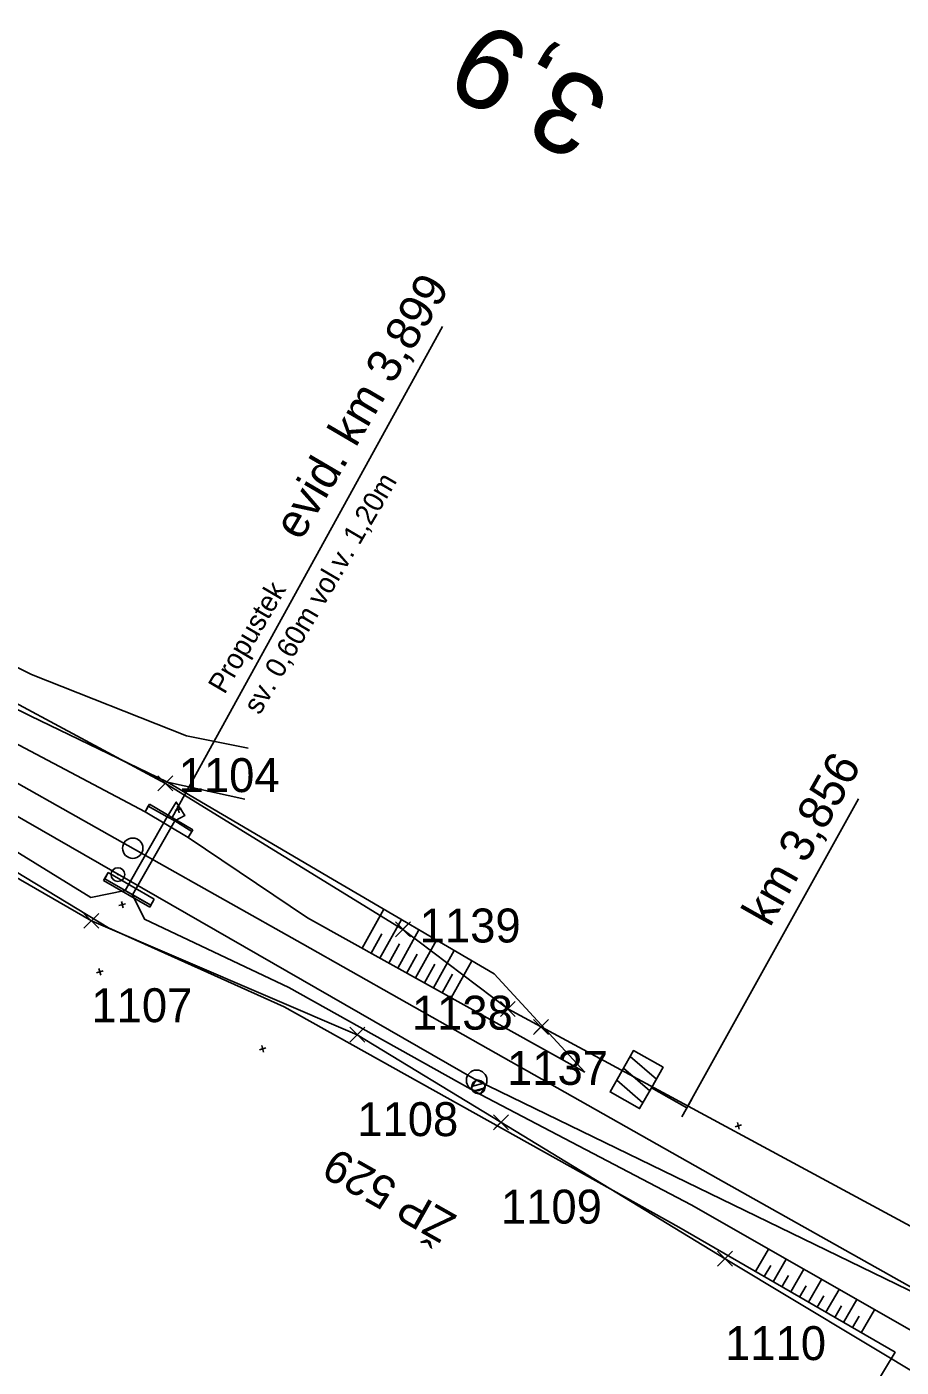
# Model space of a CAD drawing. Extents: x -738085 to -734426, y -1122197 to -1119748.
# Drawn here: x -737015.1 to -736950.7, y -1121543.6 to -1121444.9 of the extents above; entities that cross this region are included whole.
import ezdxf

# ---------------------------------------------------------------- set-up
doc = ezdxf.new("R2010")
doc.units = 0
for name, color, linetype in [('SŽDC', 7, 'Continuous'), ('Vrstva 1', 7, 'Continuous'), ('Vrstva 11', 7, 'Continuous'), ('Vrstva 12', 7, 'Continuous'), ('Vrstva 19', 7, 'Continuous'), ('Vrstva 48', 7, 'Continuous'), ('Vrstva 49', 7, 'Continuous'), ('Vrstva 51', 7, 'Continuous'), ('Vrstva 60', 7, 'Continuous'), ('Vrstva 63', 7, 'Continuous'), ('Vrstva 7', 7, 'Continuous')]:
    doc.layers.add(name, color=color, linetype=linetype)

msp = doc.modelspace()

# ---------------------------------------------------------------- linework, layer by layer
at = {"layer": 'SŽDC'}
for p, q in [((-737040.45, -1121481.52), (-737004.89, -1121500.61)), ((-737010.34, -1121510.73), (-737043.34, -1121491.76)), ((-736979.67, -1121517.22), (-736977.22, -1121518.54)), ((-736977.22, -1121518.54), (-736943.95, -1121536.5)), ((-736963.67, -1121535.61), (-736980.18, -1121525.56)), ((-736946.26, -1121546.1), (-736963.67, -1121535.61))]:
    msp.add_line(p, q, dxfattribs=at)
for points in [[(-737004.89, -1121500.61), (-736987.4, -1121511.36), (-736979.67, -1121517.22)], [(-736980.18, -1121525.56), (-736990.76, -1121519.12), (-737010.34, -1121510.73)]]:
    msp.add_lwpolyline(points, dxfattribs=at)
at = {"layer": 'Vrstva 1'}
for points in [[(-736980.547, -1121520.471), (-736994.793, -1121512.433), (-737006.133, -1121506.039), (-737037.153, -1121488.58), (-737041.663, -1121486.032), (-737045.027, -1121484.134), (-737051.946, -1121480.257), (-737060.405, -1121475.598), (-737066.648, -1121472.32), (-737074.476, -1121468.475), (-737081.816, -1121465.132)], [(-736980.547, -1121520.471), (-736994.793, -1121512.433), (-737006.133, -1121506.039), (-737037.153, -1121488.58), (-737041.663, -1121486.032), (-737045.027, -1121484.134), (-737051.946, -1121480.257), (-737060.405, -1121475.598), (-737066.648, -1121472.32), (-737074.476, -1121468.475), (-737081.816, -1121465.132)], [(-736948.039, -1121538.79), (-736964.169, -1121529.718), (-736980.547, -1121520.471)], [(-736948.039, -1121538.79), (-736964.169, -1121529.718), (-736980.547, -1121520.471)]]:
    msp.add_lwpolyline(points, dxfattribs=at)
at = {"layer": 'Vrstva 11'}
for p, q in [((-736981.444, -1121522.673), (-736982.336, -1121522.922)), ((-736981.35, -1121523.036), (-736982.23, -1121523.281))]:
    msp.add_line(p, q, dxfattribs=at)
msp.add_circle((-736981.842, -1121522.97), 0.5, dxfattribs=at)
at = {"layer": 'Vrstva 12'}
msp.add_lwpolyline([(-736981.994, -1121522.425), (-736981.297, -1121522.818), (-736981.69, -1121523.515), (-736982.387, -1121523.122), (-736981.994, -1121522.425)], dxfattribs=at)
at = {"layer": 'Vrstva 19'}
for p, q in [((-737004.398, -1121503.133), (-736984.47, -1121466.97)), ((-737006.393, -1121502.713), (-737006.073, -1121502.149)), ((-737006.148, -1121502.282), (-737006.393, -1121502.713)), ((-737003.207, -1121504.605), (-737006.393, -1121502.713)), ((-737006.073, -1121502.149), (-737006.148, -1121502.282)), ((-737006.148, -1121502.282), (-737006.148, -1121502.282)), ((-737006.148, -1121502.282), (-737004.752, -1121503.063)), ((-737006.073, -1121502.149), (-737002.875, -1121504.027)), ((-737006.073, -1121502.149), (-737006.073, -1121502.149)), ((-737002.875, -1121504.027), (-737006.073, -1121502.149)), ((-737002.875, -1121504.027), (-737006.073, -1121502.149)), ((-737007.855, -1121508.496), (-737004.752, -1121503.063)), ((-737007.855, -1121508.496), (-737004.752, -1121503.063)), ((-737007.32, -1121508.823), (-737004.192, -1121503.366)), ((-737007.32, -1121508.823), (-737004.192, -1121503.366)), ((-737004.752, -1121503.063), (-737004.752, -1121503.063)), ((-737004.752, -1121503.063), (-737004.192, -1121503.366)), ((-737004.192, -1121503.366), (-737004.192, -1121503.366)), ((-737004.192, -1121503.366), (-737002.951, -1121504.159)), ((-737002.875, -1121504.027), (-737003.207, -1121504.605)), ((-737002.951, -1121504.159), (-737003.207, -1121504.605)), ((-737002.875, -1121504.027), (-737002.951, -1121504.159)), ((-737002.951, -1121504.159), (-737002.951, -1121504.159)), ((-737002.875, -1121504.027), (-737002.875, -1121504.027)), ((-737009.439, -1121507.766), (-737009.095, -1121507.181)), ((-737009.439, -1121507.766), (-737009.361, -1121507.634)), ((-737006.028, -1121509.725), (-737009.439, -1121507.766)), ((-737009.439, -1121507.766), (-737009.439, -1121507.766)), ((-737009.361, -1121507.634), (-737009.095, -1121507.181)), ((-737009.361, -1121507.634), (-737005.956, -1121509.59)), ((-737007.855, -1121508.496), (-737009.361, -1121507.634)), ((-737009.361, -1121507.634), (-737009.361, -1121507.634)), ((-737009.095, -1121507.181), (-737005.711, -1121509.133)), ((-737007.32, -1121508.823), (-737007.855, -1121508.496)), ((-737007.855, -1121508.496), (-737007.855, -1121508.496)), ((-737005.956, -1121509.59), (-737007.32, -1121508.823)), ((-737007.32, -1121508.823), (-737007.32, -1121508.823)), ((-737005.711, -1121509.133), (-737006.028, -1121509.725)), ((-737005.956, -1121509.59), (-737006.028, -1121509.725)), ((-737006.028, -1121509.725), (-737006.028, -1121509.725)), ((-737005.956, -1121509.59), (-737005.711, -1121509.133)), ((-737005.956, -1121509.59), (-737005.956, -1121509.59))]:
    msp.add_line(p, q, dxfattribs=at)
at = {"layer": 'Vrstva 48'}
for p, q in [((-736990.397, -1121512.748), (-736988.803, -1121509.883)), ((-736989.086, -1121513.477), (-736987.509, -1121510.641)), ((-736989.742, -1121513.112), (-736988.949, -1121511.687)), ((-736987.776, -1121514.206), (-736986.214, -1121511.4)), ((-736988.431, -1121513.842), (-736987.646, -1121512.431)), ((-736986.465, -1121514.936), (-736984.92, -1121512.159)), ((-736987.12, -1121514.571), (-736986.344, -1121513.175)), ((-736985.154, -1121515.665), (-736983.625, -1121512.917)), ((-736983.843, -1121516.394), (-736982.331, -1121513.676)), ((-736985.809, -1121515.3), (-736985.041, -1121513.919)), ((-736984.499, -1121516.03), (-736983.738, -1121514.663)), ((-736961.432, -1121536.553), (-736960.476, -1121534.9)), ((-736960.783, -1121536.928), (-736960.304, -1121536.1)), ((-736960.134, -1121537.304), (-736959.173, -1121535.644)), ((-736958.836, -1121538.056), (-736957.87, -1121536.388)), ((-736959.485, -1121537.68), (-736959.003, -1121536.848)), ((-736957.537, -1121538.807), (-736956.568, -1121537.132)), ((-736958.186, -1121538.431), (-736957.703, -1121537.596)), ((-736956.888, -1121539.183), (-736956.402, -1121538.343)), ((-736956.239, -1121539.558), (-736955.265, -1121537.875)), ((-736955.59, -1121539.934), (-736955.102, -1121539.091)), ((-736954.941, -1121540.31), (-736953.962, -1121538.619)), ((-736953.643, -1121541.061), (-736952.66, -1121539.363)), ((-736954.292, -1121540.685), (-736953.801, -1121539.838))]:
    msp.add_line(p, q, dxfattribs=at)
at = {"layer": 'Vrstva 49'}
for p, q in [((-737003.701, -1121502.462), (-737004.183, -1121502.596)), ((-737003.875, -1121502.77), (-737004.009, -1121502.288)), ((-737007.855, -1121508.496), (-737007.32, -1121508.823)), ((-737007.827, -1121509.474), (-737008.309, -1121509.608)), ((-737008.001, -1121509.782), (-737008.135, -1121509.3)), ((-737009.479, -1121514.415), (-737009.961, -1121514.549)), ((-737009.653, -1121514.723), (-737009.787, -1121514.241)), ((-736997.485, -1121520.087), (-736997.967, -1121520.221)), ((-736997.659, -1121520.395), (-736997.793, -1121519.913)), ((-736962.625, -1121526.065), (-736962.759, -1121525.583)), ((-736962.451, -1121525.757), (-736962.933, -1121525.891))]:
    msp.add_line(p, q, dxfattribs=at)
for points in [[(-736973.99, -1121521.877), (-736994.429, -1121510.504), (-737003.207, -1121504.605), (-737002.951, -1121504.159), (-737004.192, -1121503.366), (-737003.454, -1121502.967), (-737004.091, -1121501.983), (-737004.752, -1121503.063), (-737006.148, -1121502.282), (-737006.393, -1121502.713), (-737041.438, -1121484.185), (-737039.81, -1121480.826)], [(-736973.99, -1121521.877), (-736980.684, -1121514.641), (-736992.594, -1121507.661), (-737004.739, -1121500.514), (-737014.862, -1121495.638), (-737027.737, -1121489.302), (-737035.093, -1121485.368), (-737037.669, -1121483.34), (-737039.81, -1121480.826)], [(-737042.621, -1121487.375), (-737044.056, -1121491.584), (-737023.648, -1121502.439), (-737009.079, -1121511.246), (-736996.149, -1121517.056), (-736967.081, -1121533.283)], [(-737007.855, -1121508.496), (-737010.391, -1121509.018), (-737023.014, -1121501.243), (-737040.001, -1121491.281), (-737042.621, -1121487.375)], [(-736966.167, -1121531.651), (-736981.69, -1121523.515), (-736982.387, -1121523.122), (-736995.797, -1121515.641), (-737006.432, -1121510.621), (-737007.32, -1121508.823)], [(-736765.343, -1121718.616), (-736768.757, -1121717.407), (-736778.323, -1121705.972), (-736786.949, -1121694.016), (-736800.729, -1121669.804), (-736811.974, -1121646.728), (-736821.953, -1121628.637), (-736834.591, -1121611.551), (-736852.315, -1121594.296), (-736852.926, -1121593.78), (-736853.864, -1121593.362), (-736873.783, -1121579.831), (-736896.637, -1121568.082), (-736921.157, -1121556.11), (-736944.745, -1121543.9), (-736949.239, -1121541.316), (-736966.167, -1121531.651)], [(-736967.081, -1121533.283), (-736951.15, -1121542.504), (-736953.651, -1121546.634)]]:
    msp.add_lwpolyline(points, dxfattribs=at)
at = {"layer": 'Vrstva 51'}
for points in [[(-737039.81, -1121480.826), (-737037.669, -1121483.34), (-737035.093, -1121485.368), (-737027.737, -1121489.302), (-737014.862, -1121495.638), (-737004.739, -1121500.514), (-736999.036, -1121501.764)], [(-736998.8, -1121498.013), (-737003.337, -1121497.104), (-737014.744, -1121492.589), (-737026.646, -1121486.677), (-737032.948, -1121483.223), (-737035.472, -1121481.101)]]:
    msp.add_lwpolyline(points, dxfattribs=at)
at = {"layer": 'Vrstva 60'}
for p, q in [((-737004.44, -1121501.06), (-737005.44, -1121500.06)), ((-737004.44, -1121500.16), (-737005.44, -1121501.16)), ((-737005.34, -1121501.06), (-737004.34, -1121500.06)), ((-737005.34, -1121500.16), (-737004.34, -1121501.16)), ((-737004.89, -1121500.61), (-737004.89, -1121500.61)), ((-737009.89, -1121511.18), (-737010.89, -1121510.18)), ((-737009.89, -1121510.28), (-737010.89, -1121511.28)), ((-737010.79, -1121511.18), (-737009.79, -1121510.18)), ((-737010.79, -1121510.28), (-737009.79, -1121511.28)), ((-737010.34, -1121510.73), (-737010.34, -1121510.73)), ((-736986.95, -1121511.81), (-736987.95, -1121510.81)), ((-736986.95, -1121510.91), (-736987.95, -1121511.91)), ((-736987.85, -1121511.81), (-736986.85, -1121510.81)), ((-736987.85, -1121510.91), (-736986.85, -1121511.91)), ((-736987.4, -1121511.36), (-736987.4, -1121511.36)), ((-736979.22, -1121517.67), (-736980.22, -1121516.67)), ((-736979.22, -1121516.77), (-736980.22, -1121517.77)), ((-736980.12, -1121517.67), (-736979.12, -1121516.67)), ((-736980.12, -1121516.77), (-736979.12, -1121517.77)), ((-736979.67, -1121517.22), (-736979.67, -1121517.22)), ((-736990.31, -1121519.57), (-736991.31, -1121518.57)), ((-736990.31, -1121518.67), (-736991.31, -1121519.67)), ((-736991.21, -1121519.57), (-736990.21, -1121518.57)), ((-736991.21, -1121518.67), (-736990.21, -1121519.67)), ((-736976.77, -1121518.99), (-736977.77, -1121517.99)), ((-736976.77, -1121518.09), (-736977.77, -1121519.09)), ((-736977.67, -1121518.99), (-736976.67, -1121517.99)), ((-736977.67, -1121518.09), (-736976.67, -1121519.09)), ((-736977.22, -1121518.54), (-736977.22, -1121518.54)), ((-736990.76, -1121519.12), (-736990.76, -1121519.12)), ((-736979.73, -1121526.01), (-736980.73, -1121525.01)), ((-736979.73, -1121525.11), (-736980.73, -1121526.11)), ((-736980.63, -1121526.01), (-736979.63, -1121525.01)), ((-736980.63, -1121525.11), (-736979.63, -1121526.11)), ((-736980.18, -1121525.56), (-736980.18, -1121525.56)), ((-736963.22, -1121536.06), (-736964.22, -1121535.06)), ((-736963.22, -1121535.16), (-736964.22, -1121536.16)), ((-736964.12, -1121536.06), (-736963.12, -1121535.06)), ((-736964.12, -1121535.16), (-736963.12, -1121536.16)), ((-736963.67, -1121535.61), (-736963.67, -1121535.61))]:
    msp.add_line(p, q, dxfattribs=at)
at = {"layer": 'Vrstva 63'}
for p, q in [((-737099.214, -1121455.153), (-736981.969, -1121522.476)), ((-736981.925, -1121522.501), (-736982.013, -1121522.451)), ((-736981.969, -1121522.476), (-736844.933, -1121589.06))]:
    msp.add_line(p, q, dxfattribs=at)
msp.add_circle((-736981.969, -1121522.476), 0.756, dxfattribs=at)
at = {"layer": 'Vrstva 7'}
for p, q in [((-736966.489, -1121524.508), (-736953.838, -1121501.738)), ((-737008.344, -1121507.349), (-737008.432, -1121507.299)), ((-736968.733, -1121522.38), (-736970.664, -1121520.715)), ((-736971.155, -1121521.586), (-736969.224, -1121523.251)), ((-736969.716, -1121524.122), (-736971.647, -1121522.457)), ((-736966.858, -1121525.161), (-736966.12, -1121523.855))]:
    msp.add_line(p, q, dxfattribs=at)
msp.add_lwpolyline([(-736966.489, -1121524.508), (-736969.101, -1121523.033), (-736968.241, -1121521.509), (-736970.418, -1121520.28), (-736972.139, -1121523.328), (-736969.962, -1121524.557), (-736969.101, -1121523.033)], dxfattribs=at)
for centre, radius in [((-737007.296, -1121505.384), 0.75), ((-737007.296, -1121505.384), 0.75), ((-737008.388, -1121507.324), 0.5)]:
    msp.add_circle(centre, radius, dxfattribs=at)

# ---------------------------------------------------------------- texts
at = {"layer": 'Vrstva 19'}
for s, height, p in [('evid. km 3,899', 2.5, (-736994.92, -1121482.83)), ('sv. 0,60m vol.v. 1,20m', 1.5, (-736997.948, -1121495.632)), ('Propustek', 1.5, (-737000.535, -1121494.113))]:
    msp.add_text(s, height=height, rotation=59.57675, dxfattribs=at).set_placement(p)
at = {"layer": 'Vrstva 60'}
for s, p in [('1104', (-737003.917, -1121501.253)), ('1139', (-736986.163, -1121512.327)), ('1107', (-737010.34, -1121518.196)), ('1138', (-736986.74, -1121518.747)), ('1137', (-736979.728, -1121522.809)), ('1108', (-736990.76, -1121526.586)), ('1109', (-736980.18, -1121533.026)), ('1110', (-736963.67, -1121543.076))]:
    msp.add_text(s, height=2.5, dxfattribs=at).set_placement(p)
at = {"layer": 'Vrstva 63'}
msp.add_text('ŽP 529', height=2.4, rotation=150.55098, dxfattribs=at).set_placement((-736983.324, -1121532.482))
at = {"layer": 'Vrstva 7'}
for s, height, rotation, p in [('3,9', 6, 150.62787, (-736971.822, -1121449.752)), ('3,9', 6, 150.62787, (-736971.822, -1121449.752)), ('km 3,856', 2.5, 60.55098, (-736960.364, -1121511.274))]:
    msp.add_text(s, height=height, rotation=rotation, dxfattribs=at).set_placement(p)

doc.saveas('drawing.dxf')
